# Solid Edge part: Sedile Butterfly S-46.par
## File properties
Title: SEDILE BUTTERFLY S-46
Author: DESYS
Template: Iso Part.par
Last saved by: PIM_1
Revision: 11
Application: Solid Edge
Accuracy: 0,990
Tipo di contenuto documento: 0
Document Number: 4010
Revision: 0
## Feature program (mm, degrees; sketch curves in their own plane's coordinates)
sketch for "unnamed Protrusion 1" plane through (10.8674, 10.8674, 0) normal (0, 0, 1) x-axis (1, 0, 0)
  line (-10.8674, -10.8674) -> (-380.8674, -10.8674)
  line (-380.8674, -10.8674) -> (-380.8674, -370.8674)
  arc centre (-300.8674, -370.8674) radius 80 from (-380.8674, -370.8674) to (-300.8674, -450.8674) ccw
  line (-300.8674, -450.8674) -> (-90.8674, -450.8674)
  arc centre (-90.8674, -370.8674) radius 80 from (-10.8674, -370.8674) to (-90.8674, -450.8674) cw
  line (-10.8674, -370.8674) -> (-10.8674, -10.8674)
  dimension (linear) = 10.8674
extrude "unnamed Protrusion 1" add finite 35 along -normal
sketch for "ScavoEstrusione_1" plane through (-185, -220, 0) normal (0, 0, 1) x-axis (1, 0, 0)
  line (0, 0) -> (0, 0)
  line (0, 0) -> (0, 0)
  line (-180, 225) -> (-180, -140)
  arc centre (-105, -140) radius 75 from (-180, -140) to (-105, -215) ccw
  line (-105, -215) -> (105, -215)
  arc centre (105, -140) radius 75 from (105, -215) to (180, -140) ccw
  line (180, -140) -> (180, 225)
  line (180, 225) -> (-180, 225)
extrude "ScavoEstrusione_1" cut finite 30 along -normal
sketch for "ProtrusioneEstrusa_3" plane through (-365, -180, -15) normal (1, 0, 0) x-axis (0, 1, 0)
  line (180, -20) -> (150, -20)
  line (150, -20) -> (150, -11)
  arc centre (166, -11) radius 16 from (166, 5) to (150, -11) ccw
  line (167.9106, 5) -> (166, 5)
  arc centre (168, -6.9997) radius 12 from (167.9106, 5) to (180, -6.9997) cw
  line (180, -20) -> (180, -6.9997)
extrude "ProtrusioneEstrusa_3" add finite 364 along +normal
sketch for "ScavoEstrusione_3" plane through (-185, -13.0447, -10) normal (0, 0, 1) x-axis (1, 0, 0)
  line (-70, 13.0447) -> (-70, -16.9553)
  line (-180, -16.9553) -> (-70, -16.9553)
  line (-180, 13.0447) -> (-180, -16.9553)
  line (-70, 13.0447) -> (-180, 13.0447)
extrude "ScavoEstrusione_3" cut finite 20 along -normal
sketch for "ScavoEstrusione_4" plane through (-130, -13.0447, -10) normal (0, 0, 1) x-axis (1, 0, 0)
  line (-115, -16.9553) -> (-115, 13.0447)
  line (5, 13.0447) -> (-115, 13.0447)
  line (5, -16.9553) -> (5, 13.0447)
  line (-115, -16.9553) -> (5, -16.9553)
extrude "ScavoEstrusione_4" cut finite 20 along -normal
sketch for "unnamed Cutout 1" plane through (-67.5, -13.0447, 0) normal (0, 0, 1) x-axis (1, 0, 0)
  line (-47.5, -16.9553) -> (-47.5, 13.0447)
  line (-47.5, 13.0447) -> (62.5, 13.0447)
  line (62.5, -16.9553) -> (62.5, 13.0447)
  line (-47.5, -16.9553) -> (62.5, -16.9553)
extrude "unnamed Cutout 1" cut to key point along -normal
sketch for "ScavoEstrusione_7" plane through (-185, 0, -17.5) normal (0, 1, 0) x-axis (-1, 0, 0)
  line (-60, -8.4998) -> (-60, 34.4272)
  line (-60, 34.4272) -> (60, 34.4272)
  line (60, -8.4998) -> (60, 34.4272)
  line (60, -8.4998) -> (-60, -8.4998)
extrude "ScavoEstrusione_7" cut finite 234 along -normal
sketch for "ScavoEstrusione_8" plane through (-185, 0, -17.5) normal (0, 1, 0) x-axis (-1, 0, 0)
  line (70, -1.1951) -> (70, 31.0532)
  line (70, 31.0532) -> (180, 32.0615)
  line (180, -1.1951) -> (180, 32.0615)
  line (70, -1.1951) -> (180, -1.1951)
extrude "ScavoEstrusione_8" cut finite 195 along -normal
sketch for "ScavoEstrusione_9" plane through (-255, -15, -19.9998) normal (-1, 0, 0) x-axis (0, -1, 0)
  circle centre (-1.8057, 2.0791) radius 3.4126
extrude "ScavoEstrusione_9" cut finite 156 along -normal
fillet "Rotondo_1" radius 10
fillet "Rotondo_2" radius 5
fillet "Rotondo_3" radius 1
fillet "Rotondo_4" radius 1
fillet "Rotondo_5" radius 15
fillet "Rotondo_7" radius 3
fillet "Rotondo_8" radius 3
fillet "Rotondo_9" radius 3
sketch for "ProtrusioneEstrusa_5" #1 plane through (-185, -216.475, -30) normal (0, 0, 1) x-axis (1, 0, 0)
  circle centre (-130, -168.3841) radius 5
sketch for "ProtrusioneEstrusa_5" #2 plane through (-185, -216.475, -30) normal (0, 0, 1) x-axis (1, 0, 0)
  circle centre (130, -168.3841) radius 5
extrude "ProtrusioneEstrusa_5" add finite 5 along +normal
fillet "Rotondo_10" radius 3
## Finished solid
Body 1: solid body, 92 faces, 204 edges, 112 vertices.
  Faces by surface: cylinder 40, torus 30, plane 18, blend 4
  Edges by curve: circle 108, line 80, intersection 12, curve on surface 2, ellipse 2
Bounding box of the edges (mm; curved faces can reach further): 370.000 x 440.000 x 35.000, from (-370, -440, -35) to (0, 0, 0).
Cylindrical faces by radius (mm): R1 x11, R3 x11, R3.4126 x2, R5 x4, R10 x2, R12 x2, R15 x2, R16 x2, R75 x2, R80 x2
Toroidal faces (ring radius, tube radius in mm): R2 r3 x1, R2.0839 r3 x1, R4 r3 x2, R6 r1 x4, R7.9161 r3 x1, R8 r3 x1, R11 r1 x8, R12 r3 x2, R15 r1 x4, R72 r3 x2, R77 r3 x4
Planar faces by outward normal: +x 4, +y 2, +z 6, -x 4, -y 1, -z 1
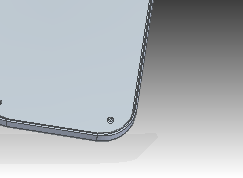
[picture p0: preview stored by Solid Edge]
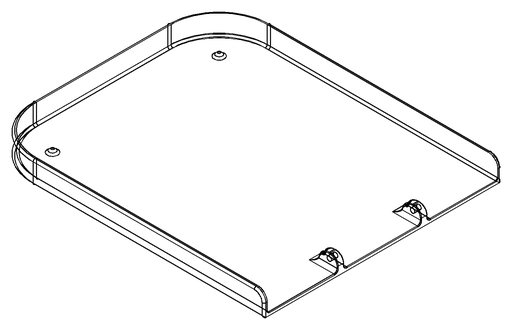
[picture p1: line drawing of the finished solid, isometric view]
